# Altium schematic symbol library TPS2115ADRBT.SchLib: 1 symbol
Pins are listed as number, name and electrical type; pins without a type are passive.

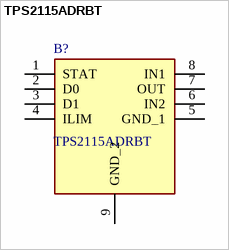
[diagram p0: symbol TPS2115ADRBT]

## TPS2115ADRBT
designator B?
Autoswitching Power Mux; Manufacturer_Name: Texas Instruments; Geometry.Height: 1mm
footprint SON65P300X300X100-9N-D
pins: 1 STAT, 2 D0, 3 D1, 4 ILIM, 5 GND_1, 6 IN2, 7 OUT, 8 IN1, 9 GND_2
